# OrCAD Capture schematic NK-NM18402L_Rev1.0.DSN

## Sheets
1 Disclaimer: title: Disclaimer; rev: V1.0; company: nuvoTon Technology Corp.
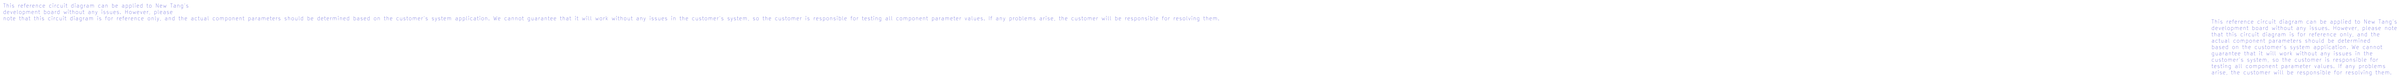
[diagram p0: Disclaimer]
2 NM18402Y Demo Board: size A4; title: NM18402Y Demo Board
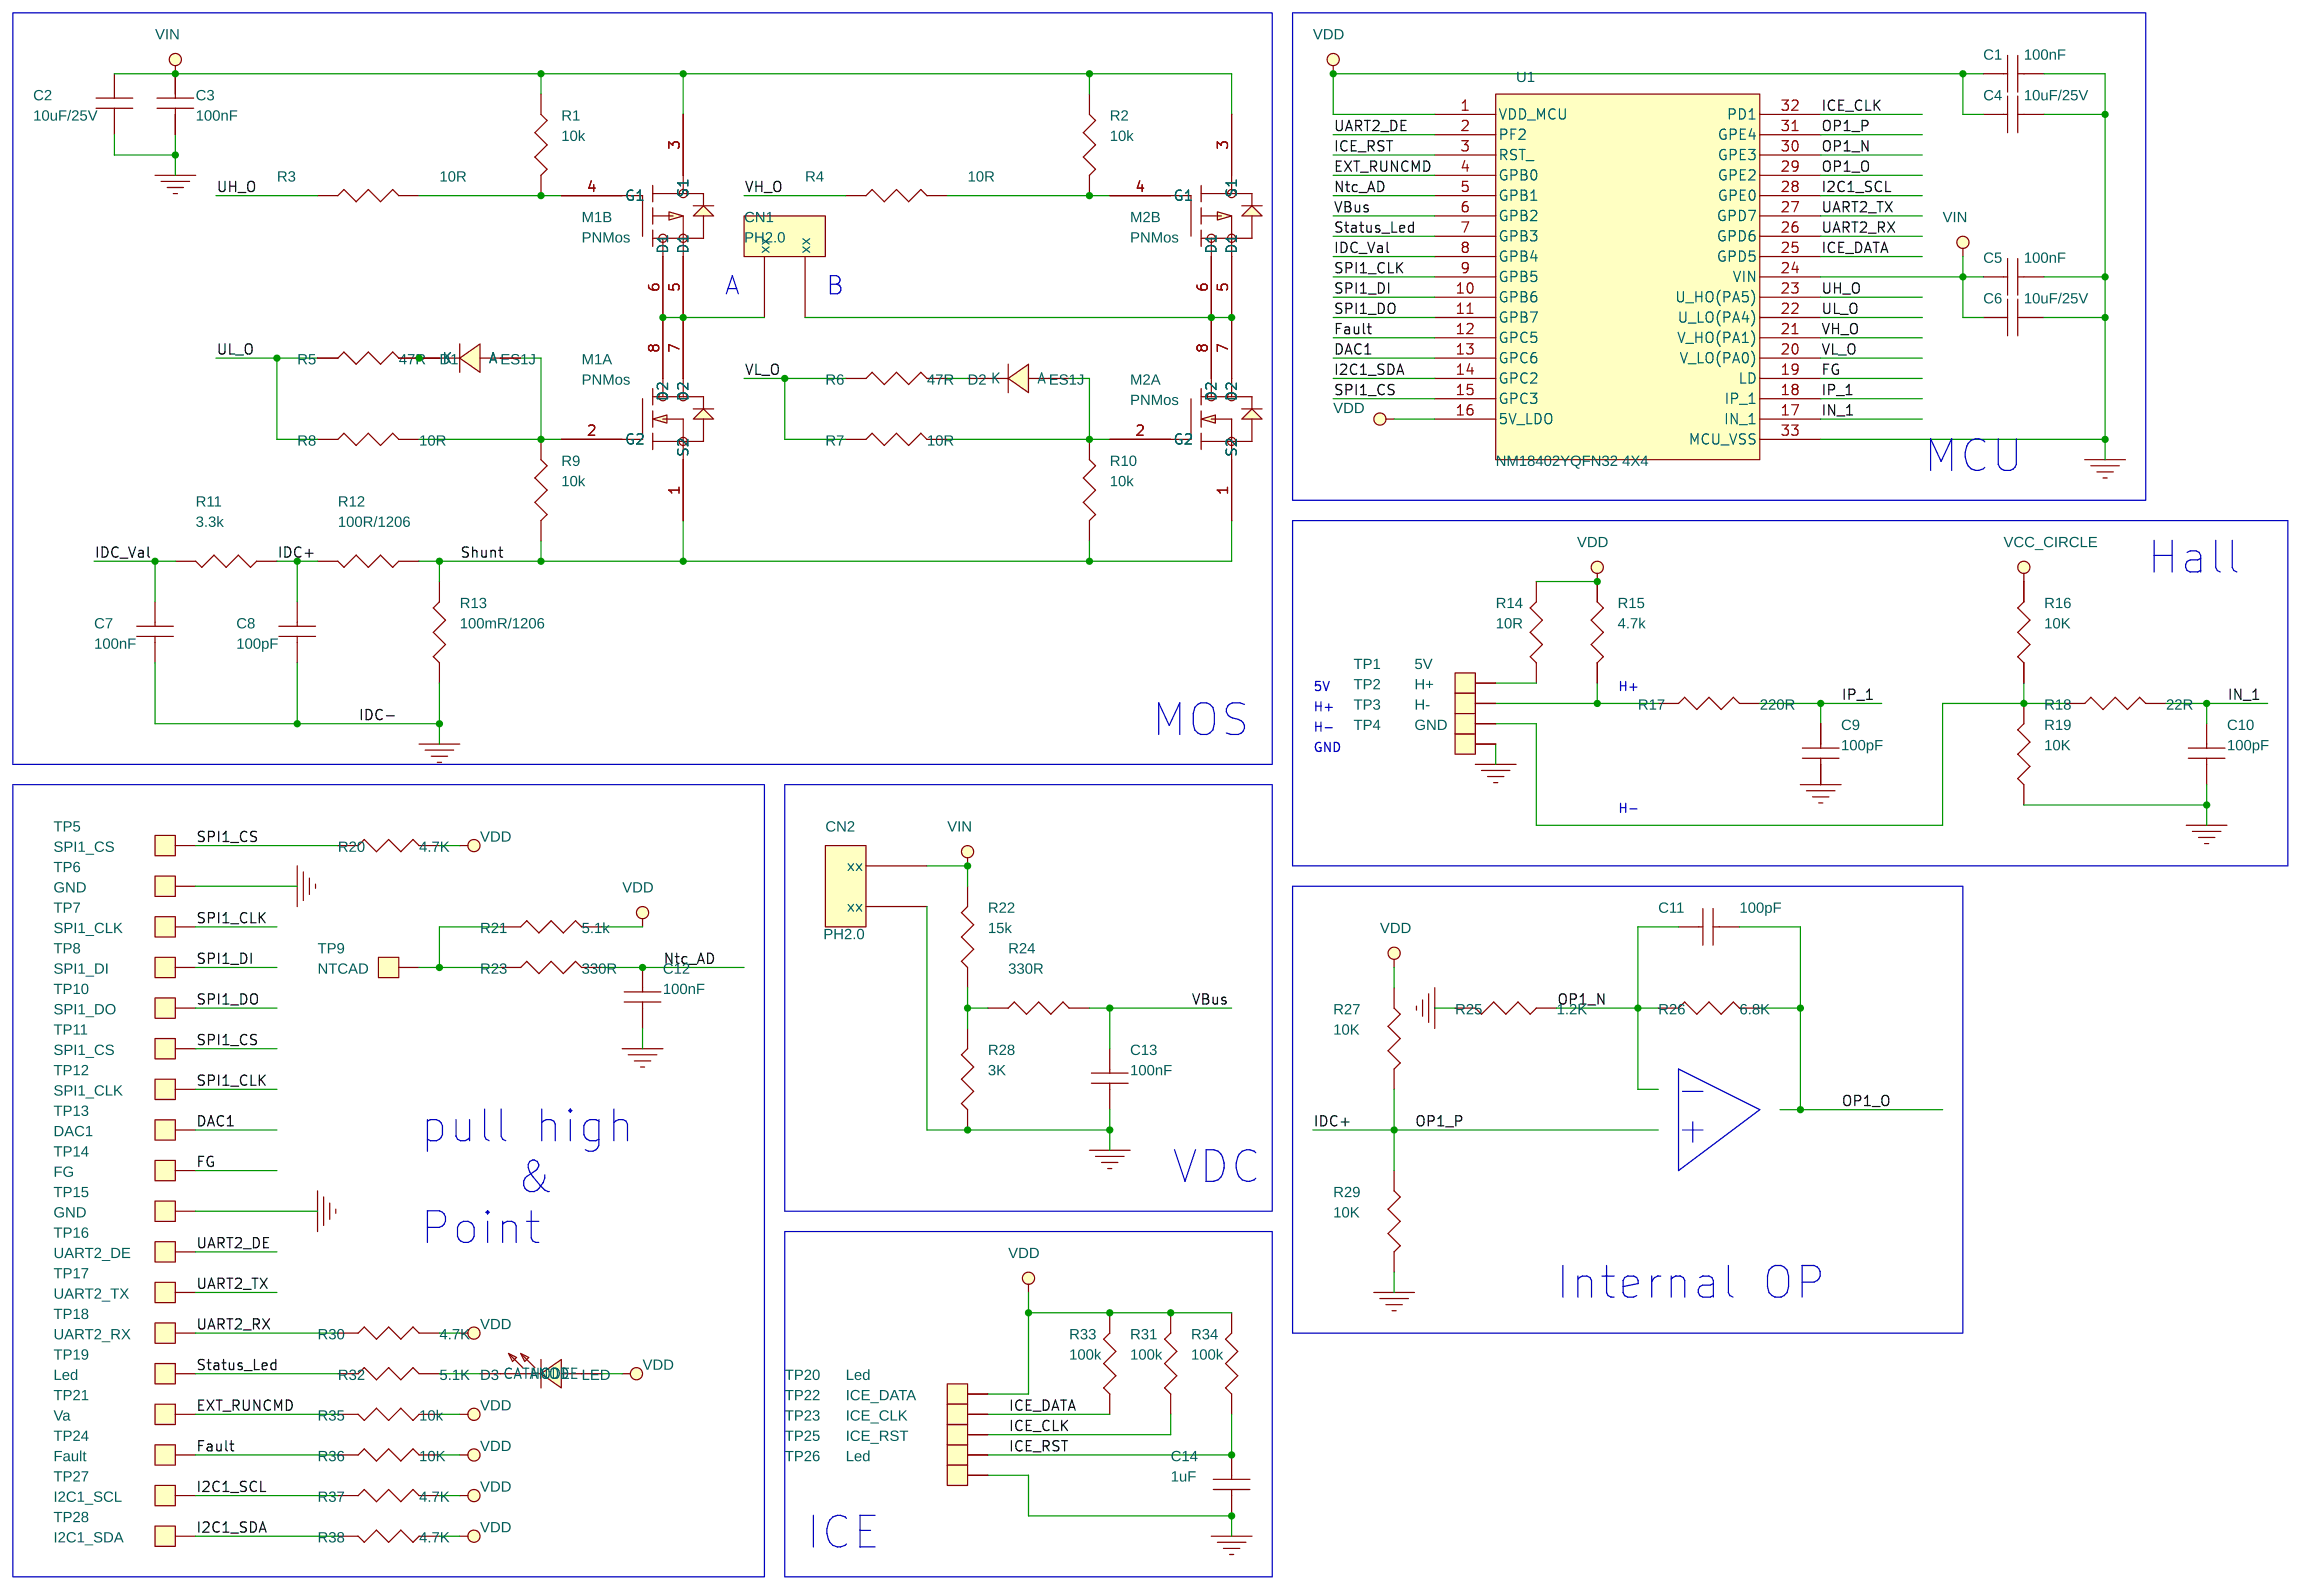
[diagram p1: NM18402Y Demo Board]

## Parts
C1  100nF  [C0805]
C2  10uF/25V  [CAP_8_2.54]
C3  100nF  [C0805]
C4  10uF/25V  [CAP_8_2.54]
C5  100nF  [C0805]
C6  10uF/25V  [CAP_8_2.54]
C7  100nF  [C0805]
C8  100pF  [C0805]
C9  100pF  [C0805]
C10  100pF  [C0805]
C11  100pF  [C0805]
C12  100nF  [C0805]
C13  100nF  [C0805]
C14  1uF  [C0805]
CN1  PH2.0  [SIP-2P]
CN2  PH2.0  [SIP-2P]
D1  ES1J  [DO-214AC]
D2  ES1J  [DO-214AC]
D3  LED  [LED_5MM]
M1  PNMos  [SOIC_8PIN_150MIL_1.27]  (sections A,B)
M2  PNMos  [SOIC_8PIN_150MIL_1.27]  (sections A,B)
R1  10k  [R0805]
R2  10k  [R0805]
R3  10R  [R0805]
R4  10R  [R0805]
R5  47R  [R0805]
R6  47R  [R0805]
R7  10R  [R0805]
R8  10R  [R0805]
R9  10k  [R0805]
R10  10k  [R0805]
R11  3.3k  [R0805]
R12  100R/1206  [R0805]
R13  100mR/1206  [R1206]
R14  10R  [R0805]
R15  4.7k  [R0805]
R16  10K  [R0805]
R17  220R  [R0805]
R18  22R  [R0805]
R19  10K  [R0805]
R20  4.7K  [R0805]
R21  5.1k  [R0805]
R22  15k  [R0805]
R23  330R  [R0805]
R24  330R  [R0805]
R25  1.2K  [R0805]
R26  6.8K  [R0805]
R27  10K  [R0805]
R28  3K  [R0805]
R29  10K  [R0805]
R30  4.7K  [R0805]
R31  100k  [R0805]
R32  5.1K  [R0805]
R33  100k  [R0805]
R34  100k  [R0805]
R35  10k  [R0805]
R36  10K  [R0805]
R37  4.7K  [R0805]
R38  4.7K  [R0805]
TP1  5V  [TEST/1S/30mil]
TP2  H+  [TEST/1S/30mil]
TP3  H-  [TEST/1S/30mil]
TP4  GND  [TEST/1S/30mil]
TP5  SPI1_CS  [TEST/1S/30mil]
TP6  GND  [TEST/1S/30mil]
TP7  SPI1_CLK  [TEST/1S/30mil]
TP8  SPI1_DI  [TEST/1S/30mil]
TP9  NTCAD  [TEST/1S/30mil]
TP10  SPI1_DO  [TEST/1S/30mil]
TP11  SPI1_CS  [TEST/1S/30mil]
TP12  SPI1_CLK  [TEST/1S/30mil]
TP13  DAC1  [TEST/1S/30mil]
TP14  FG  [TEST/1S/30mil]
TP15  GND  [TEST/1S/30mil]
TP16  UART2_DE  [TEST/1S/30mil]
TP17  UART2_TX  [TEST/1S/30mil]
TP18  UART2_RX  [TEST/1S/30mil]
TP19  Led  [TEST/1S/30mil]
TP20  Led  [TEST/1S/30mil]
TP21  Va  [TEST/1S/30mil]
TP22  ICE_DATA  [TEST/1S/30mil]
TP23  ICE_CLK  [TEST/1S/30mil]
TP24  Fault  [TEST/1S/30mil]
TP25  ICE_RST  [TEST/1S/30mil]
TP26  Led  [TEST/1S/30mil]
TP27  I2C1_SCL  [TEST/1S/30mil]
TP28  I2C1_SDA  [TEST/1S/30mil]
U1  NM18402YQFN32 4X4  [QFN32L_4X4MM_EP]

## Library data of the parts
C1-C9 C11-C14 = C1
C10 = Cap0
CN1 CN2 = CN
D1 D2 = D
D3 = LED
M1 M2 = PNMos
R1-R10 R14-R30 R32 R35-R38 = R_2
R11-R13 R31 R33 R34 = R
TP1-TP28 = Test_point
U1 = NM18402YQFN32_4X4_0

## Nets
GND: C1.2 C2.2 C3.2 C4.2 C5.2 C6.2 C7.2 C8.2 C9.2 C10.2 C12.2 C13.2 C14.2 CN2.2(xx) R13.1 R19.1 R25.1 R28.1 R29.1 TP4.1(TP) TP6.1(TP) TP15.1(TP) TP26.1(TP) U1.33(MCU_VSS)
VBus: C13.1 R24.2 U1.6(GPB2)
VDD: C1.1 C4.1 D3.1(ANODE) R14.2 R15.1 R16.2 R20.2 R21.2 R27.2 R30.1 R31.2 R33.2 R34.2 R35.2 R36.2 R37.2 R38.1 TP20.1(TP) U1.1(VDD_MCU) U1.16(5V_LDO)
Vin: C2.1 C3.1 C5.1 C6.1 CN2.1(xx) M1.3(S1) M2.3(S1) R1.1 R2.1 R22.2 U1.24(VIN)
DAC1: TP13.1(TP) U1.13(GPC6)
EXT_RUNCMD: R35.1 TP21.1(TP) U1.4(GPB0)
Fault: R36.1 TP24.1(TP) U1.12(GPC5)
FG: TP14.1(TP) U1.19(LD)
I2C1_SCL: R37.1 TP27.1(TP) U1.28(GPE0)
I2C1_SDA: R38.2 TP28.1(TP) U1.14(GPC2)
ICE_CLK: R31.1 TP23.1(TP) U1.32(PD1)
ICE_DATA: R33.1 TP22.1(TP) U1.25(GPD5)
ICE_RST: C14.1 R34.1 TP25.1(TP) U1.3(RST_)
IDC+: C8.1 R11.1 R12.2 R27.1 R29.2 U1.31(GPE4)
IDC_Val: C7.1 R11.2 U1.8(GPB4)
IN_1: C10.1 R18.2 U1.17(IN_1)
IP_1: C9.1 R17.2 U1.18(IP_1)
Ntc_AD: C12.1 R23.2 U1.5(GPB1)
OP1_N: C11.1 R25.2 R26.1 U1.30(GPE3)
OP1_O: C11.2 R26.2 U1.29(GPE2)
Shunt: M1.1(S2) M2.1(S2) R9.2 R10.2 R12.1 R13.2
SPI1_CLK: TP7.1(TP) TP12.1(TP) U1.9(GPB5)
SPI1_CS: R20.1 TP5.1(TP) TP11.1(TP) U1.15(GPC3)
SPI1_DI: TP8.1(TP) U1.10(GPB6)
SPI1_DO: TP10.1(TP) U1.11(GPB7)
Status_Led: R32.2 TP19.1(TP) U1.7(GPB3)
UART2_DE: TP16.1(TP) U1.2(PF2)
UART2_RX: R30.2 TP18.1(TP) U1.26(GPD6)
UART2_TX: TP17.1(TP) U1.27(GPD7)
UH_O: R3.1 U1.23(U_HO(PA5))
UL_O: R5.1 R8.1 U1.22(U_LO(PA4))
VH_O: R4.1 U1.21(V_HO(PA1))
VL_O: R6.1 R7.1 U1.20(V_LO(PA0))
N158369: R15.2 R17.1 TP2.1(TP)
N158417: R16.1 R18.1 R19.2 TP3.1(TP)
N158617: CN1.2(xx) M1.5(D1) M1.6(D1) M1.7(D2) M1.8(D2)
N158621: CN1.1(xx) M2.5(D1) M2.6(D1) M2.7(D2) M2.8(D2)
N158869: D1.1(A) M1.2(G2) R8.2 R9.1
N159023: R21.1 R23.1 TP9.1(TP)
N160197: D2.1(A) M2.2(G2) R7.2 R10.1
N160241: M1.4(G1) R1.2 R3.2
N160273: M2.4(G1) R2.2 R4.2
N160277: D1.2(K) R5.2
N160443: D2.2(K) R6.2
N160535: D3.2(CATHODE) R32.1
N161151: R22.1 R24.1 R28.2
N161483: R14.1 TP1.1(TP)

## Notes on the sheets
sheet 1
- This reference circuit diagram can be applied to New Tang's
  development board without any issues. However, please
  note that this circuit diagram is for reference only, and the actual component parameters should be determined based on the customer's system application. We cannot guarantee that it will work without any issues in the customer's system, so the customer is responsible for testing all component parameter values. If any problems arise, the customer will be responsible for resolving them.
- This reference circuit diagram can be applied to New Tang's
  development board without any issues. However, please note
  that this circuit diagram is for reference only, and the
  actual component parameters should be determined
  based on the customer's system application. We cannot
  guarantee that it will work without any issues in the
  customer's system, so the customer is responsible for
  testing all component parameter values. If any problems
  arise, the customer will be responsible for resolving them.
- This reference circuit diagram can be applied to Nuvoton development
  board without any issues. However, please note that this circuit diagram
  is for reference only, and the actual component parameters should be
  determined based on the customer's system application. We cannot guarantee
  that it will work without any issues in the customer's system, so the
  customer is responsible for testing all component parameter  values.
  If any problems arise, the customer will be responsible for resolving them.
sheet 2
- A
- B
- MCU
- Hall
- 5V
- H+
- MOS
- H+
- H-
- GND
- H-
- pull high
      &
  Point
- VDC
- Internal OP
- ICE
